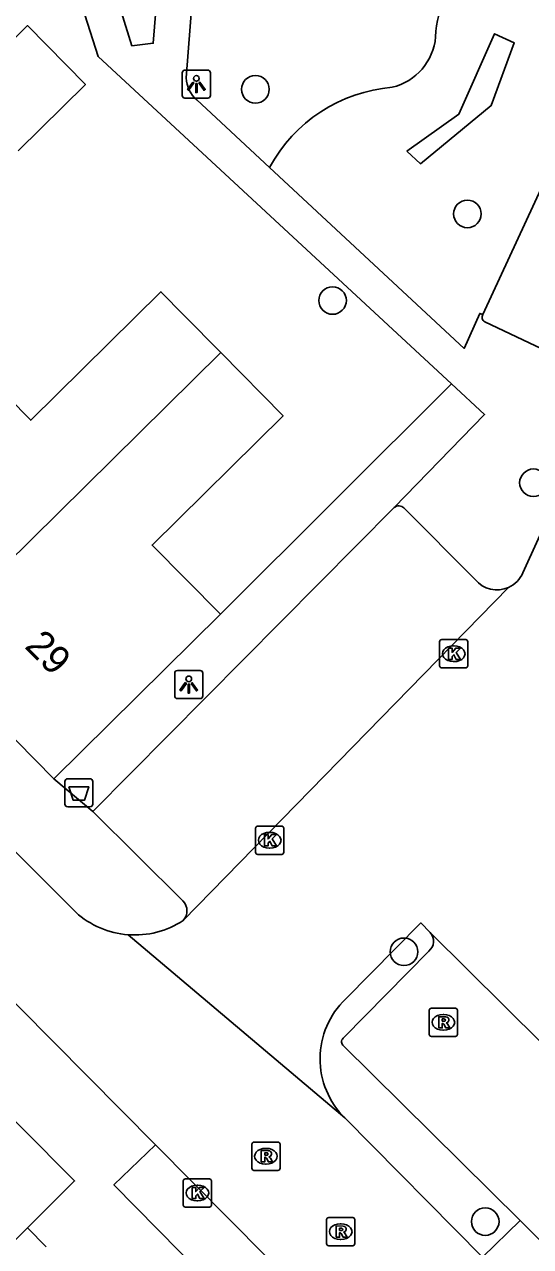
# Model space of a CAD drawing. Extents: x 160107 to 160928, y 382056 to 382918.
# Drawn here: x 160812.03 to 160829.99, y 382688.58 to 382731.92 of the extents above; entities that cross this region are included whole.
import ezdxf

# ---------------------------------------------------------------- set-up
doc = ezdxf.new("R2010")
doc.units = 0
for name, color, linetype in [('IMGEO_Afvalbak', 7, 'Continuous'), ('IMGEO_Boom', 7, 'Continuous'), ('IMGEO_Groenvoorziening', 7, 'Continuous'), ('IMGEO_Haag', 7, 'Continuous'), ('IMGEO_Kolk', 7, 'Continuous'), ('IMGEO_Lichtpunt', 7, 'Continuous'), ('IMGEO_Pand', 7, 'Continuous'), ('IMGEO_Pand_nummerreeks', 7, 'Continuous'), ('IMGEO_Parkeervlak_open', 7, 'Continuous'), ('IMGEO_Rijbaan_lokaal_open', 7, 'Continuous'), ('IMGEO_Rioolput', 7, 'Continuous'), ('IMGEO_Voetpad_open', 7, 'Continuous')]:
    doc.layers.add(name, color=color, linetype=linetype)

msp = doc.modelspace()

# ---------------------------------------------------------------- linework, layer by layer
at = {"layer": 'IMGEO_Afvalbak'}
for p, q in [((160813.468, 382704.271), (160813.468, 382705.071)), ((160813.468, 382705.071), (160813.468, 382704.271)), ((160813.568, 382705.171), (160814.358, 382705.171)), ((160814.358, 382705.171), (160813.568, 382705.171)), ((160814.458, 382705.071), (160814.458, 382704.271)), ((160814.458, 382704.271), (160814.458, 382705.071)), ((160814.358, 382704.171), (160813.568, 382704.171)), ((160813.568, 382704.171), (160814.358, 382704.171))]:
    msp.add_line(p, q, dxfattribs=at)
msp.add_lwpolyline([(160813.611, 382704.885), (160814.315, 382704.885), (160814.166, 382704.415), (160813.76, 382704.415), (160813.611, 382704.885)], dxfattribs=at)
for centre, start, end in [((160813.568, 382705.071), 90, 180), ((160813.568, 382705.071), 90, 180), ((160814.358, 382705.071), 0, 90), ((160814.358, 382705.071), 360, 90), ((160813.568, 382704.271), 180, 270), ((160813.568, 382704.271), 180, 270), ((160814.358, 382704.271), 270, 0), ((160814.358, 382704.271), 270, 0)]:
    msp.add_arc(centre, 0.1, start, end, dxfattribs=at)
at = {"layer": 'IMGEO_Boom'}
for centre in [(160820.226, 382729.623), (160827.746, 382725.204), (160822.964, 382722.132), (160830.089, 382715.667), (160825.497, 382699.031), (160828.379, 382689.46)]:
    msp.add_circle(centre, 0.489, dxfattribs=at)
at = {"layer": 'IMGEO_Groenvoorziening'}
msp.add_lwpolyline([(160818.986, 382711.001), (160827.188, 382719.173)], dxfattribs=at)
for centre, radius, start, end in [((160829.463, 382731.443), 2.843, 117.1803, 179.174), ((160824.592, 382731.671), 2.037, 283.8964, 354.7273), ((160825.535, 382724.242), 5.471, 94.7645, 151.5529)]:
    msp.add_arc(centre, radius, start, end, dxfattribs=at)
at = {"layer": 'IMGEO_Haag'}
msp.add_lwpolyline([(160825.597, 382727.429), (160827.445, 382728.736), (160828.704, 382731.597), (160829.41, 382731.268), (160828.589, 382729.045), (160826.082, 382726.982), (160825.597, 382727.429)], dxfattribs=at)
at = {"layer": 'IMGEO_Kolk'}
for p, q in [((160826.835, 382710.103), (160827.687, 382710.103)), ((160826.76, 382709.177), (160826.76, 382710.029)), ((160827.248, 382709.883), (160827.273, 382709.883)), ((160827.761, 382710.029), (160827.761, 382709.177)), ((160827.271, 382709.323), (160827.246, 382709.323)), ((160827.687, 382709.103), (160826.835, 382709.103)), ((160820.233, 382702.561), (160820.233, 382703.413)), ((160820.308, 382703.487), (160821.16, 382703.487)), ((160820.721, 382703.267), (160820.746, 382703.267)), ((160821.234, 382703.413), (160821.234, 382702.561)), ((160820.744, 382702.707), (160820.719, 382702.707)), ((160821.16, 382702.487), (160820.308, 382702.487)), ((160817.668, 382690.049), (160817.668, 382690.901)), ((160817.743, 382690.975), (160818.595, 382690.975)), ((160818.156, 382690.755), (160818.181, 382690.755)), ((160818.669, 382690.901), (160818.669, 382690.049)), ((160818.179, 382690.195), (160818.154, 382690.195)), ((160818.595, 382689.975), (160817.743, 382689.975))]:
    msp.add_line(p, q, dxfattribs=at)
for points in [[(160826.835, 382710.103), (160827.687, 382710.103)], [(160826.76, 382709.177), (160826.76, 382710.029)], [(160827.081, 382709.803), (160827.204, 382709.803), (160827.204, 382709.652), (160827.334, 382709.803), (160827.498, 382709.803), (160827.352, 382709.652), (160827.505, 382709.403), (160827.353, 382709.403), (160827.268, 382709.567), (160827.204, 382709.5), (160827.204, 382709.403), (160827.081, 382709.403), (160827.081, 382709.803)], [(160827.761, 382710.029), (160827.761, 382709.177)], [(160827.687, 382709.103), (160826.835, 382709.103)], [(160820.233, 382702.561), (160820.233, 382703.413)], [(160820.308, 382703.487), (160821.16, 382703.487)], [(160820.554, 382703.187), (160820.677, 382703.187), (160820.677, 382703.036), (160820.807, 382703.187), (160820.971, 382703.187), (160820.825, 382703.036), (160820.978, 382702.787), (160820.826, 382702.787), (160820.741, 382702.951), (160820.677, 382702.884), (160820.677, 382702.787), (160820.554, 382702.787), (160820.554, 382703.187)], [(160821.234, 382703.413), (160821.234, 382702.561)], [(160821.16, 382702.487), (160820.308, 382702.487)], [(160817.668, 382690.049), (160817.668, 382690.901)], [(160817.743, 382690.975), (160818.595, 382690.975)], [(160817.989, 382690.675), (160818.112, 382690.675), (160818.112, 382690.524), (160818.242, 382690.675), (160818.406, 382690.675), (160818.26, 382690.524), (160818.413, 382690.275), (160818.261, 382690.275), (160818.176, 382690.439), (160818.112, 382690.372), (160818.112, 382690.275), (160817.989, 382690.275), (160817.989, 382690.675)], [(160818.669, 382690.901), (160818.669, 382690.049)], [(160818.595, 382689.975), (160817.743, 382689.975)]]:
    msp.add_lwpolyline(points, dxfattribs=at)
for centre, start, end in [((160826.837, 382710.027), 91.552, 178.448), ((160826.837, 382710.027), 91.552, 178.448), ((160827.685, 382710.027), 1.552, 88.448), ((160827.685, 382710.027), 1.552, 88.448), ((160826.837, 382709.179), 181.552, 268.448), ((160826.837, 382709.179), 181.552, 268.448), ((160827.685, 382709.179), 271.552, 358.448), ((160827.685, 382709.179), 271.552, 358.448), ((160820.31, 382703.411), 91.552, 178.448), ((160820.31, 382703.411), 91.552, 178.448), ((160821.158, 382703.411), 1.552, 88.448), ((160821.158, 382703.411), 1.552, 88.448), ((160820.31, 382702.563), 181.552, 268.448), ((160820.31, 382702.563), 181.552, 268.448), ((160821.158, 382702.563), 271.552, 358.448), ((160821.158, 382702.563), 271.552, 358.448), ((160817.745, 382690.899), 91.552, 178.448), ((160817.745, 382690.899), 91.552, 178.448), ((160818.593, 382690.899), 1.552, 88.448), ((160818.593, 382690.899), 1.552, 88.448), ((160817.745, 382690.051), 181.552, 268.448), ((160817.745, 382690.051), 181.552, 268.448), ((160818.593, 382690.051), 271.552, 358.448), ((160818.593, 382690.051), 271.552, 358.448)]:
    msp.add_arc(centre, 0.0765, start, end, dxfattribs=at)
for centre, major_axis, ratio, start_param, end_param in [((160827.247, 382709.603), (-0.387, 0.002), 0.722429, 4.712389, 7.853982), ((160827.272, 382709.603), (-0.39, 0.002), 0.717154, 1.570796, 4.712389), ((160820.72, 382702.987), (-0.387, 0.002), 0.722429, 4.712389, 7.853982), ((160820.745, 382702.987), (-0.39, 0.002), 0.717154, 1.570796, 4.712389), ((160818.155, 382690.475), (-0.387, 0.002), 0.722429, 4.712389, 7.853982), ((160818.18, 382690.475), (-0.39, 0.002), 0.717154, 1.570796, 4.712389)]:
    msp.add_ellipse(centre, major_axis=major_axis, ratio=ratio, start_param=start_param, end_param=end_param, dxfattribs=at)
at = {"layer": 'IMGEO_Lichtpunt'}
for p, q in [((160817.634, 382730.212), (160817.634, 382729.405)), ((160817.634, 382730.212), (160817.634, 382729.405)), ((160818.536, 382730.307), (160817.728, 382730.307)), ((160818.536, 382730.307), (160817.728, 382730.307)), ((160818.63, 382729.405), (160818.63, 382730.212)), ((160818.63, 382729.405), (160818.63, 382730.212)), ((160817.728, 382729.311), (160818.536, 382729.311)), ((160817.728, 382729.311), (160818.536, 382729.311)), ((160817.364, 382708.913), (160817.364, 382708.106)), ((160817.364, 382708.913), (160817.364, 382708.106)), ((160818.266, 382709.008), (160817.458, 382709.008)), ((160818.266, 382709.008), (160817.458, 382709.008)), ((160818.36, 382708.106), (160818.36, 382708.913)), ((160818.36, 382708.106), (160818.36, 382708.913)), ((160817.458, 382708.012), (160818.266, 382708.012)), ((160817.458, 382708.012), (160818.266, 382708.012))]:
    msp.add_line(p, q, dxfattribs=at)
for points in [[(160818.008, 382729.876), (160818.047, 382729.848), (160817.859, 382729.586), (160817.821, 382729.613), (160818.008, 382729.876)], [(160818.11, 382729.828), (160818.157, 382729.828), (160818.157, 382729.506), (160818.11, 382729.506), (160818.11, 382729.828)], [(160818.22, 382729.848), (160818.258, 382729.875), (160818.445, 382729.613), (160818.406, 382729.585), (160818.22, 382729.848)], [(160817.738, 382708.577), (160817.777, 382708.549), (160817.589, 382708.287), (160817.551, 382708.314), (160817.738, 382708.577)], [(160817.84, 382708.529), (160817.887, 382708.529), (160817.887, 382708.207), (160817.84, 382708.207), (160817.84, 382708.529)], [(160817.95, 382708.549), (160817.988, 382708.576), (160818.175, 382708.314), (160818.136, 382708.286), (160817.95, 382708.549)]]:
    msp.add_lwpolyline(points, dxfattribs=at)
for centre in [(160818.133, 382730.01), (160817.863, 382708.711)]:
    msp.add_circle(centre, 0.0994, dxfattribs=at)
for centre, start, end in [((160817.728, 382730.212), 90, 180), ((160817.728, 382730.212), 90, 180), ((160818.536, 382730.212), 0, 90), ((160818.536, 382730.212), 0, 90), ((160817.728, 382729.405), 180, 270), ((160817.728, 382729.405), 180, 270), ((160818.536, 382729.405), 270, 0), ((160818.536, 382729.405), 270, 360), ((160817.458, 382708.913), 90, 180), ((160817.458, 382708.913), 90, 180), ((160818.266, 382708.913), 0, 90), ((160818.266, 382708.913), 0, 90), ((160817.458, 382708.106), 180, 270), ((160817.458, 382708.106), 180, 270), ((160818.266, 382708.106), 270, 0), ((160818.266, 382708.106), 270, 360)]:
    msp.add_arc(centre, 0.0946, start, end, dxfattribs=at)
at = {"layer": 'IMGEO_Pand'}
for points in [[(160809.748, 382729.526), (160812.137, 382731.884), (160814.195, 382729.798), (160811.806, 382727.44)], [(160809.852, 382720.326), (160812.259, 382717.887), (160816.872, 382722.442), (160817.699, 382721.603), (160818.996, 382720.289)], [(160808.44, 382709.868), (160818.996, 382720.289)], [(160818.996, 382720.289), (160821.211, 382718.045), (160816.563, 382713.457), (160818.986, 382711.001)], [(160818.986, 382711.001), (160813.078, 382705.17)], [(160813.078, 382705.17), (160808.44, 382709.868)], [(160812.145, 382689.243), (160810.27, 382687.376), (160806.751, 382683.872), (160805.649, 382684.98), (160806.982, 382686.307), (160804.962, 382688.336), (160803.909, 382686.641), (160801.448, 382684.19), (160798.572, 382687.079), (160804.595, 382693.076), (160808.138, 382696.603)], [(160808.138, 382696.603), (160813.813, 382690.904), (160812.145, 382689.243)]]:
    msp.add_lwpolyline(points, dxfattribs=at)
at = {"layer": 'IMGEO_Parkeervlak_open'}
for points in [[(160835.311, 382736.794), (160828.298, 382721.634)], [(160814.462, 382704.005), (160825.154, 382714.785)], [(160826.374, 382699.055), (160823.368, 382695.99)], [(160823.328, 382695.721), (160829.618, 382689.503)]]:
    msp.add_lwpolyline(points, dxfattribs=at)
for centre, radius, start, end in [((160826.098, 382699.41), 0.449, 307.8456, 42.2375), ((160823.45, 382695.84), 0.17, 118.6281, 224.4562)]:
    msp.add_arc(centre, radius, start, end, dxfattribs=at)
at = {"layer": 'IMGEO_Rijbaan_lokaal_open'}
for points in [[(160832.435, 382718.448), (160829.713, 382712.474)], [(160829.204, 382711.954), (160817.664, 382700.142)], [(160813.852, 382700.432), (160810.91, 382703.363)], [(160808.229, 382700.703), (160816.679, 382692.183)], [(160823.418, 382697.355), (160826.089, 382700.053), (160826.431, 382699.712)], [(160826.431, 382699.712), (160837.035, 382689.203)], [(160823.394, 382693.141), (160815.709, 382699.637)], [(160828.283, 382688.201), (160823.394, 382693.141)], [(160816.679, 382692.183), (160828.426, 382680.337)]]:
    msp.add_lwpolyline(points, dxfattribs=at)
for centre, radius, start, end in [((160828.797, 382712.861), 0.994, 294.1503, 337.0746), ((160815.95, 382702.767), 3.14, 228.0586, 265.5889), ((160815.947, 382702.75), 3.123, 265.6196, 303.3476), ((160825.468, 382695.236), 2.948, 134.0599, 225.2875)]:
    msp.add_arc(centre, radius, start, end, dxfattribs=at)
at = {"layer": 'IMGEO_Rioolput'}
for p, q in [((160826.393, 382696.103), (160826.393, 382696.955)), ((160826.468, 382697.029), (160827.32, 382697.029)), ((160826.881, 382696.809), (160826.906, 382696.809)), ((160827.394, 382696.955), (160827.394, 382696.103)), ((160826.904, 382696.249), (160826.879, 382696.249)), ((160827.32, 382696.029), (160826.468, 382696.029)), ((160820.099, 382691.353), (160820.099, 382692.205)), ((160820.174, 382692.279), (160821.026, 382692.279)), ((160820.587, 382692.059), (160820.612, 382692.059)), ((160821.1, 382692.205), (160821.1, 382691.353)), ((160820.61, 382691.499), (160820.585, 382691.499)), ((160821.026, 382691.279), (160820.174, 382691.279)), ((160822.751, 382688.679), (160822.751, 382689.531)), ((160822.826, 382689.605), (160823.678, 382689.605)), ((160823.239, 382689.385), (160823.264, 382689.385)), ((160823.752, 382689.531), (160823.752, 382688.679)), ((160823.262, 382688.825), (160823.237, 382688.825)), ((160823.678, 382688.605), (160822.826, 382688.605))]:
    msp.add_line(p, q, dxfattribs=at)
for points in [[(160826.393, 382696.103), (160826.393, 382696.955)], [(160826.468, 382697.029), (160827.32, 382697.029)], [(160826.982, 382696.727), (160826.73, 382696.729), (160826.73, 382696.329)], [(160826.908, 382696.648), (160826.854, 382696.648), (160826.854, 382696.567)], [(160827.394, 382696.955), (160827.394, 382696.103)], [(160826.73, 382696.329), (160826.854, 382696.329), (160826.854, 382696.491), (160826.865, 382696.491)], [(160826.854, 382696.567), (160826.906, 382696.567)], [(160826.912, 382696.462), (160826.983, 382696.329), (160827.123, 382696.329), (160827.058, 382696.455)], [(160827.32, 382696.029), (160826.468, 382696.029)], [(160820.099, 382691.353), (160820.099, 382692.205)], [(160820.174, 382692.279), (160821.026, 382692.279)], [(160820.688, 382691.977), (160820.436, 382691.979), (160820.436, 382691.579)], [(160820.614, 382691.898), (160820.56, 382691.898), (160820.56, 382691.817)], [(160821.1, 382692.205), (160821.1, 382691.353)], [(160820.436, 382691.579), (160820.56, 382691.579), (160820.56, 382691.741), (160820.571, 382691.741)], [(160820.56, 382691.817), (160820.612, 382691.817)], [(160820.618, 382691.712), (160820.689, 382691.579), (160820.829, 382691.579), (160820.764, 382691.705)], [(160821.026, 382691.279), (160820.174, 382691.279)], [(160822.751, 382688.679), (160822.751, 382689.531)], [(160822.826, 382689.605), (160823.678, 382689.605)], [(160823.34, 382689.303), (160823.088, 382689.305), (160823.088, 382688.905)], [(160823.752, 382689.531), (160823.752, 382688.679)], [(160823.088, 382688.905), (160823.212, 382688.905), (160823.212, 382689.067), (160823.223, 382689.067)], [(160823.266, 382689.224), (160823.212, 382689.224), (160823.212, 382689.143)], [(160823.212, 382689.143), (160823.264, 382689.143)], [(160823.27, 382689.038), (160823.341, 382688.905), (160823.481, 382688.905), (160823.416, 382689.031)], [(160823.678, 382688.605), (160822.826, 382688.605)]]:
    msp.add_lwpolyline(points, dxfattribs=at)
for centre, radius, start, end in [((160826.47, 382696.953), 0.0765, 91.552, 178.448), ((160826.47, 382696.953), 0.0765, 91.552, 178.448), ((160826.914, 382696.552), 0.0964, 77.0061, 93.1865), ((160826.928, 382696.609), 0.0378, 276.6634, 79.6772), ((160826.981, 382696.617), 0.109, 350.3612, 89.416), ((160827.318, 382696.953), 0.0765, 1.552, 88.448), ((160827.318, 382696.953), 0.0765, 1.552, 88.448), ((160826.864, 382696.438), 0.0533, 26.0293, 88.6989), ((160826.89, 382696.756), 0.19, 274.7715, 282.9687), ((160826.979, 382696.617), 0.112, 277.5842, 350.9817), ((160826.963, 382696.402), 0.108, 29.5134, 73.7905), ((160826.47, 382696.105), 0.0765, 181.552, 268.448), ((160826.47, 382696.105), 0.0765, 181.552, 268.448), ((160827.318, 382696.105), 0.0765, 271.552, 358.448), ((160827.318, 382696.105), 0.0765, 271.552, 358.448), ((160820.176, 382692.203), 0.0765, 91.552, 178.448), ((160820.176, 382692.203), 0.0765, 91.552, 178.448), ((160820.62, 382691.802), 0.0964, 77.0061, 93.1865), ((160820.634, 382691.859), 0.0378, 276.6634, 79.6772), ((160820.687, 382691.867), 0.109, 350.3612, 89.416), ((160820.685, 382691.867), 0.112, 277.5842, 350.9817), ((160821.024, 382692.203), 0.0765, 1.552, 88.448), ((160821.024, 382692.203), 0.0765, 1.552, 88.448), ((160820.57, 382691.688), 0.0533, 26.0293, 88.6989), ((160820.596, 382692.006), 0.19, 274.7715, 282.9687), ((160820.669, 382691.652), 0.108, 29.5134, 73.7905), ((160820.176, 382691.355), 0.0765, 181.552, 268.448), ((160820.176, 382691.355), 0.0765, 181.552, 268.448), ((160821.024, 382691.355), 0.0765, 271.552, 358.448), ((160821.024, 382691.355), 0.0765, 271.552, 358.448), ((160822.828, 382689.529), 0.0765, 91.552, 178.448), ((160822.828, 382689.529), 0.0765, 91.552, 178.448), ((160823.339, 382689.193), 0.109, 350.3612, 89.416), ((160823.676, 382689.529), 0.0765, 1.552, 88.448), ((160823.676, 382689.529), 0.0765, 1.552, 88.448), ((160823.222, 382689.014), 0.0533, 26.0293, 88.6989), ((160823.248, 382689.332), 0.19, 274.7715, 282.9687), ((160823.272, 382689.128), 0.0964, 77.0061, 93.1865), ((160823.286, 382689.185), 0.0378, 276.6634, 79.6772), ((160823.337, 382689.193), 0.112, 277.5842, 350.9817), ((160823.321, 382688.978), 0.108, 29.5134, 73.7905), ((160822.828, 382688.681), 0.0765, 181.552, 268.448), ((160822.828, 382688.681), 0.0765, 181.552, 268.448), ((160823.676, 382688.681), 0.0765, 271.552, 358.448), ((160823.676, 382688.681), 0.0765, 271.552, 358.448)]:
    msp.add_arc(centre, radius, start, end, dxfattribs=at)
for centre, major_axis, ratio, start_param, end_param in [((160826.88, 382696.529), (-0.387, 0.002), 0.722429, 4.712389, 7.853982), ((160826.905, 382696.529), (-0.39, 0.002), 0.717154, 1.570796, 4.712389), ((160820.586, 382691.779), (-0.387, 0.002), 0.722429, 4.712389, 7.853982), ((160820.611, 382691.779), (-0.39, 0.002), 0.717154, 1.570796, 4.712389), ((160823.238, 382689.105), (-0.387, 0.002), 0.722429, 4.712389, 7.853982), ((160823.263, 382689.105), (-0.39, 0.002), 0.717154, 1.570796, 4.712389)]:
    msp.add_ellipse(centre, major_axis=major_axis, ratio=ratio, start_param=start_param, end_param=end_param, dxfattribs=at)
at = {"layer": 'IMGEO_Voetpad_open'}
for points in [[(160813.607, 382739.317), (160814.046, 382738.873), (160814.334, 382736.045), (160815.844, 382731.167), (160816.605, 382731.255), (160817.442, 382741.576)], [(160827.188, 382719.173), (160814.653, 382730.787), (160812.95, 382736.12), (160811.706, 382737.281), (160813.607, 382739.317)], [(160818.14, 382734.749), (160817.776, 382730.026)], [(160818.147, 382729.245), (160820.725, 382726.848)], [(160828.298, 382721.634), (160828.185, 382721.676), (160827.626, 382720.435), (160820.725, 382726.848)], [(160831.938, 382719.69), (160828.36, 382721.376)], [(160825.154, 382714.785), (160828.355, 382718.092), (160827.188, 382719.173)], [(160825.494, 382714.774), (160828.027, 382712.233)], [(160814.462, 382704.005), (160813.078, 382705.17)], [(160817.656, 382700.837), (160814.462, 382704.005)], [(160826.925, 382678.87), (160815.21, 382690.76), (160816.679, 382692.183)], [(160829.618, 382689.503), (160828.283, 382688.201)], [(160833.497, 382685.627), (160829.618, 382689.503)], [(160812.805, 382688.565), (160812.145, 382689.243)]]:
    msp.add_lwpolyline(points, dxfattribs=at)
for centre, radius, start, end in [((160818.867, 382730.066), 1.092, 182.0846, 228.7338), ((160828.443, 382721.532), 0.177, 145.0836, 241.9415), ((160825.318, 382714.606), 0.243, 43.6797, 132.6142), ((160828.798, 382712.862), 0.994, 219.2033, 294.1258), ((160817.299, 382700.485), 0.501, 316.773, 44.5459)]:
    msp.add_arc(centre, radius, start, end, dxfattribs=at)

# ---------------------------------------------------------------- texts
at = {"layer": 'IMGEO_Pand_nummerreeks'}
msp.add_text('29', height=1, rotation=314.6278, dxfattribs=at).set_placement((160812.011, 382709.837))

doc.saveas('drawing.dxf')
